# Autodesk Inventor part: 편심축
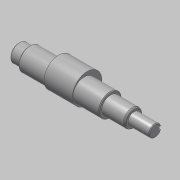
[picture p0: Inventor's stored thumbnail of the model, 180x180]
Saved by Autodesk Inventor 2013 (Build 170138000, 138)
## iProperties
Created: 2015-10
Part Number: 편심축
Document SubType Name: Modeling
Designer: mdu
Density: 1 g/cm^3
Material: 강철, 연강
Mass: 168.947 g
Surface Area: 248.524 cm^2
Volume: 168.947 cm^3
Author: mdu
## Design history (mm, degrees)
sketch "스케치1"
  geometry: L1 (-20.5, -41.331)-(-20.5, 32.669) reference; L2 (7.5, -30.031)-(7.5, 21.369) reference; L3 (135.5, -30.331)-(135.5, 21.669) reference; L4 (121.5, 21.369)-(121.5, -30.031) reference; L5 (184.5, -4.331)-(-7.5, -4.331); L6 (184.5, -4.331)-(184.5, 4.169); L7 (154.5, 8.169)-(121.5, 8.169); L8 (121.5, 8.169)-(121.5, 11.669); L9 (121.5, 11.669)-(7.5, 11.669); L10 (7.5, 11.669)-(7.5, 8.169); L11 (7.5, 8.169)-(-7.5, 8.169); L12 (-7.5, 8.169)-(-7.5, -4.331); L13 (154.5, 8.169)-(154.5, 4.169); L14 (154.5, 4.169)-(184.5, 4.169); C1 r 32.5 at (64.5, -4.331) reference; 1 further point
  constraints: 21 end point, 8 perpendicular, 5 point on line, 1 collinear
  dimensions: "d1" = 25 diameter of L11 L5; "d2" = 32 diameter of L9 L5; "d4" = 15 distance of L10.end L11.end; "d15" = 33 distance of L7.start L7.end; "d26" = 30 distance of L13.end L6.end; "d36" = 17 diameter of L14 L5
revolve "회전1" sketch "스케치1" stored, may be unused: angle "d6" = 90 deg
node "작업 평면1"
sketch "스케치2"
  geometry: C1 r 16 at (0, 0) reference; C2 r 20.75 at (0, 4)
  constraints: 1 centre point, 1 vertical alignment
  dimensions: "d34" = 4 distance of C2.centre C1.centre; "d35" = 41.5 diameter of C2
extrude "돌출1" join sketch "스케치2" stored distance "d9" = 40; taper "d10" = 0 deg
chamfer "모따기1" distance "d11" = 1; stored, may be unused: second distance "d12" = 2, angle "d13" = 45 deg
node "작업 평면2"
sketch "스케치3"
  geometry: L1 (-15, -7.5)-(-15, 7.5) reference; L2 (-15, 2.5)-(0.5, 2.5); L3 (0.5, -2.5)-(-15, -2.5); A1 r 2.5 centre (0.5, 0) between (0.5, -2.5) and (0.5, 2.5); 2 further points
  constraints: 4 end point, 2 perpendicular, 2 point on circle, 2 point on line, 2 tangent, 1 centre point, 1 horizontal alignment, 1 midpoint
  dimensions: "d16" = 18 dimension on A1 L1; "d17" = 5 distance between parallel lines of L3 L2
extrude "돌출2" cut sketch "스케치3" distance "d18" = 3; taper "d19" = 0 deg
chamfer "모따기2" distance "d37" = 2.15; stored, may be unused: second distance "d38" = 2, angle "d39" = 30 deg
fillet "모깎기1" dims "d40" = 1, "d41" = 2
node "솔리드1"
node "참조1"
node "참조2"
node "참조3"
node "참조4"
node "참조5"
other parameters: "d30" = 35
